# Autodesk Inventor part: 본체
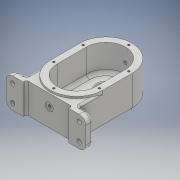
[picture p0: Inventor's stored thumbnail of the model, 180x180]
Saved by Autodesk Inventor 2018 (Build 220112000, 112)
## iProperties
Created: 2021-05
Part Number: 본체
Material: 일반
Document SubType Name: Modeling
Designer: Admin
Density: 1 g/cm^3
Appearance: 기본값
Author: Admin
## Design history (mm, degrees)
sketch "스케치1"
  geometry: L1 (0, -22.5)-(0, 22.5); L2 (-40, -22.5)-(-40, 22.5); L3 (40, 22.5)-(40, -22.5); A1 r 40 centre (0, -22.5) between (-40, -22.5) and (40, -22.5); A2 r 40 centre (0, 22.5) between (40, 22.5) and (-40, 22.5); 2 further points
  constraints: 8 end point, 4 point on circle, 4 tangent, 2 centre point, 1 coincident, 1 midpoint, 1 parallel, 1 vertical
  dimensions: "d0" = 80 distance between parallel lines of L3 L2; "d1" = 45 distance of L1.start L1.end
extrude "돌출1" new body sketch "스케치1" stored distance "d2" = 49; taper "d3" = 0 deg
sketch "스케치3"
  geometry: L1 (-69.5, 21.5)-(-59.5, 21.5); L2 (-59.5, 21.5)-(-59.5, -24.5); L3 (-59.5, -24.5)-(-69.5, -24.5); L4 (-69.5, -24.5)-(-69.5, 21.5); L5 (-62.5, -24.5)-(-22.5, -24.5) reference; L6 (22.5, 24.5)-(22.5, -24.5) reference; L7 (22.5, 24.5)-(22.5, 24.5) reference; L8 (22.5, 24.5)-(22.5, -24.5) reference; L9 (22.5, -24.5)-(22.5, -24.5) reference; L10 (62.5, -24.5)-(62.5, 24.5) reference; 1 further point
  constraints: 8 end point, 2 parallel, 1 collinear, 1 horizontal, 1 perpendicular
  dimensions: "d8" = 46 distance of L3.end L1.start; "d13" = 132 distance between parallel lines of L10 L4; "d14" = 10 distance between parallel lines of L4 L2
extrude "돌출3" join sketch "스케치3" stored distance "d11" = 122; taper "d12" = 0 deg
sketch "스케치4"
  geometry: L1 (-55.199, 46)-(24.801, 46); L2 (24.801, 46)-(24.801, 0); L3 (24.801, 0)-(-55.199, 0); L4 (-55.199, 0)-(-55.199, 46); L5 (-100.599, 21.5)-(70.201, 21.5) reference; L6 (-15.199, 55.8)-(-15.199, -12.8) reference; L7 (45.801, 46)-(-76.199, 46) reference; 2 further points
  constraints: 8 end point, 2 midpoint, 2 parallel, 1 horizontal, 1 perpendicular, 1 other
  dimensions: "d15" = 46 distance of L1.end L2.end; "d16" = 80 distance of L1.start L1.end
extrude "돌출4" join sketch "스케치4" distance "d17" = 40; taper "d18" = 0 deg
sketch "스케치5"
  geometry: L1 (-40, 22.5)-(-40, -22.5) reference; L2 (40, -22.5)-(40, 22.5) reference; L3 (0, 22.5)-(0, -22.5); L4 (-30, 22.5)-(-30, -22.5); L5 (30, -22.5)-(30, 22.5); A1 r 40 centre (0, -22.5) between (-40, -22.5) and (40, -22.5) reference; A2 r 40 centre (0, 22.5) between (40, 22.5) and (-40, 22.5) reference; A3 r 30 centre (0, 22.5) between (30, 22.5) and (-30, 22.5); A4 r 30 centre (0, -22.5) between (-30, -22.5) and (30, -22.5); 2 further points
  constraints: 8 end point, 4 point on circle, 4 tangent, 2 centre point, 1 midpoint, 1 parallel, 1 vertical
  dimensions: "d19" = 30 radius of A3
extrude "돌출5" cut sketch "스케치5" distance "d20" = 41; taper "d21" = 0 deg
sketch "스케치6"
  geometry: L1 (0, 22.5)-(0, -22.5); L2 (-26, 22.5)-(-26, -22.5); L3 (26, -22.5)-(26, 22.5); A1 r 26 centre (0, 22.5) between (26, 22.5) and (-26, 22.5); A2 r 26 centre (0, -22.5) between (-26, -22.5) and (26, -22.5); 2 further points
  constraints: 8 end point, 4 point on circle, 4 tangent, 2 centre point, 1 coincident, 1 midpoint, 1 parallel, 1 vertical
  dimensions: "d22" = 52 distance between parallel lines of L3 L2; "d23" = 45 distance of L1.start L1.end
extrude "돌출6" join sketch "스케치6" distance "d24" = 8; taper "d25" = 0 deg
sketch "스케치7"
  geometry: L1 (0, -22.5)-(0, 22.5); L2 (-26, -22.5)-(-26, -7.5); L3 (26, -7.5)-(26, -22.5); L4 (26, 22.5)-(26, -22.5) reference; L5 (26, 22.5)-(-26, 22.5); L6 (-26, -7.5)-(26, -7.5); A1 r 26 centre (0, -22.5) between (-26, -22.5) and (26, -22.5); A2 r 26 centre (0, 22.5) between (26, 22.5) and (-26, 22.5); 2 further points
  constraints: 12 end point, 4 point on circle, 4 tangent, 2 centre point, 2 perpendicular, 1 coincident, 1 midpoint, 1 parallel, 1 point on line, 1 vertical
  dimensions: "d29" = 30 distance between parallel lines of L6 L5
extrude "돌출7" join sketch "스케치7" distance "d30" = 3; taper "d31" = 0 deg
sketch "스케치8"
  geometry: L1 (22.5, 59.59)-(22.5, -61.115); L2 (22.5, 24.5)-(22.5, -16.5) reference; L3 (22.5, -16.5)-(36.5, -16.5); L4 (22.5, -16.5)-(52.5, -16.5) reference; L5 (36.5, -16.5)-(36.5, -24.2); L6 (36.2, -24.5)-(33.5, -24.5); L7 (33.5, -24.5)-(33.5, -28.5); L8 (33.5, -28.5)-(36.5, -28.5); L9 (36.5, -28.5)-(36.5, -32.5); L10 (22.5, -32.5)-(48.5, -32.5) reference; L11 (36.5, -32.5)-(22.5, -32.5); L12 (22.5, -32.5)-(22.5, -16.5); A1 r 0.3 centre (36.2, -24.2) between (36.2, -24.5) and (36.5, -24.2); 3 further points
  constraints: 18 end point, 7 point on line, 3 perpendicular, 2 point on circle, 2 tangent, 2 vertical, 1 centre point, 1 collinear, 1 horizontal, 1 midpoint
  dimensions: "d32" = 8 distance of L3.end point (36.5, -24.5); "d33" = 4 distance of L8.end L9.end; "d34" = 22 diameter of L7 L1; "d35" = 28 diameter of L9 L1; "d36" = 0.3 radius of A1
revolve "회전1" sketch "스케치8" stored, may be unused: angle "d37" = 90 deg
sketch "스케치9"
  geometry: L1 (-22.5, 24.5)-(-22.5, -16.5) reference; L2 (-22.5, 33.135)-(-22.5, -85.217); L3 (-8.5, -16.5)-(-8.5, -24.2); L4 (-8.8, -24.5)-(-12.5, -24.5); L5 (-12.5, -24.5)-(-12.5, -25.5); L6 (-15.5, -28.5)-(-22.5, -28.5); L7 (-22.5, -28.5)-(-22.5, -16.5); L8 (-22.5, -16.5)-(-8.5, -16.5); L9 (-22.5, -16.5)-(22.5, -16.5) reference; A1 r 3 centre (-15.5, -25.5) between (-15.5, -28.5) and (-12.5, -25.5); A2 r 0.3 centre (-8.8, -24.2) between (-8.8, -24.5) and (-8.5, -24.2); 4 further points
  constraints: 14 end point, 6 point on line, 4 point on circle, 4 tangent, 3 perpendicular, 2 centre point, 2 collinear, 2 vertical, 1 midpoint
  dimensions: "d38" = 8 distance of L3.start point (-8.5, -24.5); "d39" = 28 diameter of L3 L2; "d40" = 20 diameter of L5 L2; "d41" = 4 distance of L4.end point (-12.5, -28.5); "d42" = 3 radius of A1; "d43" = 0.3 radius of A2
revolve "회전2" sketch "스케치9" stored, may be unused: angle "d44" = 90 deg
fillet "모깎기1" dims "d45" = 10
sketch "스케치10"
  geometry: L1 (11, 46)-(-91, 46) reference; L2 (21, 10)-(21, 36) reference; L3 (-91, 0)-(11, 0) reference; L4 (-101, 36)-(-101, 10) reference; A1 r 10 centre (-91, 36) between (-91, 46) and (-101, 36) reference; A2 r 10 centre (11, 36) between (21, 36) and (11, 46) reference; A3 r 10 centre (11, 10) between (11, 0) and (21, 10) reference; A4 r 10 centre (-91, 10) between (-101, 10) and (-91, 0) reference; 5 further points
  constraints: 4 coincident
hole "구멍1" sketch "스케치10" at (-91, 10), (-91, 36), (11, 36), (11, 10) diameter "d46" = 6.6; stored, may be unused: countersink angle "d50" = 90 deg, drill point angle "d52" = 118 deg; dims "d47" = 6, "d48" = 11, "d49" = 2, "d51" = 11
node "작업 평면1"
sketch "스케치11"
  geometry: L1 (91, 49)-(11, 49) reference; L2 (51, -23)-(51, 61) reference; C1 r 6 at (51, 28); 1 further point
  constraints: 1 centre point, 1 point on line
  dimensions: "d54" = 12 diameter of C1; "d55" = 21 distance from line of L1 C1.centre
extrude "돌출8" join sketch "스케치11" stored distance "d56" = 3; taper "d57" = 0 deg
sketch "스케치12"
  geometry: L1 (51, -47)-(-51, -47) reference; L2 (-35, -47)-(35, -47); L3 (35, -47)-(35, -42); L4 (35, -42)-(-35, -42); L5 (-35, -42)-(-35, -47); L6 (0, -74)-(0, 115) reference; 1 further point
  constraints: 8 end point, 2 parallel, 1 horizontal, 1 perpendicular, 1 point on line, 1 other
  dimensions: "d58" = 70 distance of L3.end L4.end; "d59" = 5 distance of L2.end L3.end
extrude "돌출9" cut sketch "스케치12" extent not by distance; stored distance "d60" = 3; taper "d61" = 0 deg
sketch "스케치13"
  geometry: C1 r 6 at (0, 0) reference; 2 further points
  constraints: 1 coincident
hole "구멍2" sketch "스케치13" at (0, 0) diameter "d62" = 4.917; stored, may be unused: countersink angle "d66" = 90 deg, drill point angle "d68" = 118 deg; dims "d63" = 135, "d64" = 11, "d65" = 2, "d67" = 17.1
sketch "스케치14"
  geometry: C1 r 6 at (35, -18) reference; C2 r 6 at (35, -18); 1 further point
  constraints: 1 centre point, 1 coincident
  dimensions: "d69" = 12 diameter of C2
extrude "돌출10" cut sketch "스케치14" distance "d70" = 1; taper "d71" = 0 deg
sketch "스케치15"
  geometry: L1 (0, -22.5)-(0, 22.5); L2 (35, -22.5)-(35, 22.5); L3 (-35, 22.5)-(-35, -22.5); C1 r 11 at (0, 22.5) reference; C2 r 10 at (0, -22.5) reference; A1 r 35 centre (0, -22.5) between (-35, -22.5) and (35, -22.5); A2 r 35 centre (0, 22.5) between (35, 22.5) and (-35, 22.5); 8 further points
  constraints: 8 end point, 6 point on circle, 4 coincident, 4 tangent, 2 centre point, 1 midpoint, 1 parallel, 1 vertical
  dimensions: "d72" = 70 diameter of A2
hole "구멍3" sketch "스케치15" at (0, 57.5), (35, 22.5), (-35, 22.5), (-35, -22.5), (35, -22.5), (0, -57.5) diameter "d73" = 3.242; stored, may be unused: countersink angle "d77" = 90 deg, drill point angle "d79" = 118 deg; dims "d74" = 8, "d75" = 11, "d76" = 2, "d78" = 10
sketch "스케치16" dims "d80" = 40
  geometry: L1 (0, -96.5)-(0, 92.5) reference; C1 r 14 at (0, 22.5) reference; 5 further points
  constraints: 1 coincident, 1 point on line, 1 vertical alignment, 6 other
  dimensions: "d83" = 360 deg dimension on C1.centre point (0, 42.5) (derived)
hole "구멍4" sketch "스케치16" at (0, 42.5), (-17.321, 12.5), (17.321, 12.5) diameter "d85" = 3.242; stored, may be unused: countersink angle "d89" = 90 deg, drill point angle "d91" = 118 deg; dims "d86" = 8, "d87" = 11, "d88" = 2, "d90" = 10
fillet "모깎기2" dims "d92" = 5
fillet "모깎기3" dims "d93" = 3
fillet "모깎기4" dims "d94" = 3
chamfer "모따기1" distance "d95" = 1; stored, may be unused: second distance "d96" = 2, angle "d97" = 45 deg
sketch "스케치17"
  geometry: L1 (0, -96.506)-(0, 92.534) reference; L2 (-51, -69.5)-(-61, -69.5) reference; 2 further points
  constraints: 1 point on line, 1 other
  dimensions: "d98" = 12 distance from line of L2 point (0, -57.5)
feature "엠보싱1" sketch "스케치17" dims "d0" = 80, "d1" = 45, "d43" = 0.3, "d83" = 360 deg (derived), "d99" = 0.5, "d100" = 0
node "솔리드1"
node "투영된 루프1"
node "투영된 루프2"
node "투영된 루프3"
other parameters: "d53" = -135
